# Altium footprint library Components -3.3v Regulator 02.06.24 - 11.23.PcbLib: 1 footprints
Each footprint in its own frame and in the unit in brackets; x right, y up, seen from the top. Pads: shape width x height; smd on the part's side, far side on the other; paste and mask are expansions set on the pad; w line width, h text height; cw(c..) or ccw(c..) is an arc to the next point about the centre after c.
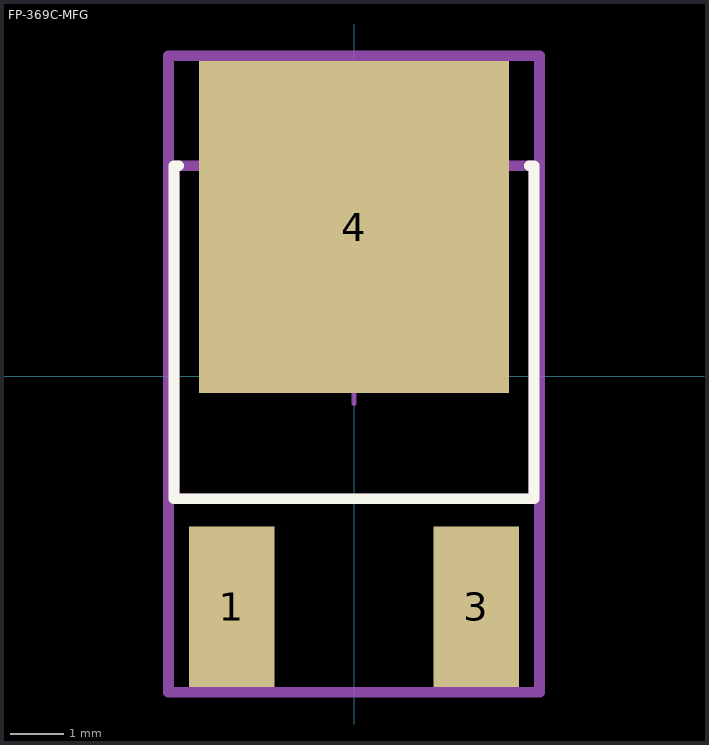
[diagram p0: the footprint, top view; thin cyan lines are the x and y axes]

## FP-369C-MFG [mm]
pads (3):
  rect 1.6x3 smd paste+0 mask+0: 1(-2.285,-4.3) 3(2.285,-4.3)
  rect 5.8x6.2 smd paste+0 mask+0: 4(0,2.79)
Top Overlay:
  lines w0.2: -3.275,3.935 -3.365,3.935 -3.365,-2.285 3.365,-2.285 3.365,3.935 3.275,3.935
Top Assembly:
  lines w0.2: -3.465,-5.9 -3.465,5.99 3.465,5.99 3.465,-5.9 -3.465,-5.9
  text ".Designator" at 0,0.044 h1
Top 3D Body:
  lines w0.2: -3.365,-2.285 -3.365,3.935 3.365,3.935 3.365,-2.285 -3.365,-2.285
Top Courtyard:
  lines w0.2: -3.465,-5.9 -3.465,5.99 3.465,5.99 3.465,-5.9 -3.465,-5.9
Top Component Center:
  lines w0.1: -0.5,0 0.5,0 ; 0,-0.5 0,0.5
3D body "IC_ON_Semiconductor_MC7805CDTG_eec.STEP": height 0.25, standoff 0, extent -3.465,-5.9 3.465,5.99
